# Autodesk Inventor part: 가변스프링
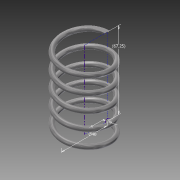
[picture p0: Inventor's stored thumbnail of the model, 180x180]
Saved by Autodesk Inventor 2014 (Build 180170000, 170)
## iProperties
Created: 2017-01
Part Number: 가변스프링
Material: Stainless Steel
Document SubType Name: Modeling
Designer: user
Density: 8.08 g/cm^3
Appearance: Semi-Polished
Mass: 62.9918 g
Surface Area: 78.9831 cm^2
Volume: 7.79602 cm^3
Author: user
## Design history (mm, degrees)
sketch "Sketch1"
  geometry: L1 (0, 0)-(20, 0); L2 (20, 0)-(20, 67.25); L3 (20, 67.25)-(0, 67.25); L4 (0, 67.25)-(0, 0); C1 r 2 at (20, 0)
  constraints: 8 end point, 2 parallel, 1 centre point, 1 coincident, 1 horizontal, 1 perpendicular
  dimensions: "d0" = 40 diameter of L2 L4; "d1" = 67.25 distance between parallel lines of L3 L1 (derived); "d2" = 4 diameter of C1
coil "Coil1" pitch "d3" = 10; turns "d5" = 5; dims "d4" = 67.25 (= d1), "d6" = 0, angle "d7" = 90 deg, angle "d8" = 90 deg, "d9" = 0, "d10" = 0
sketch "Sketch2"
  geometry: L1 (0, 18)-(0, 22) reference; 1 further point
  constraints: 1 vertical alignment
extrude "Extrusion1" cut sketch "Sketch2" distance "d11" = 10; taper "d12" = 0 deg
workplane "Work Plane1"
sketch "Sketch3"
  geometry: L1 (0, 18)-(0, 22) reference; 1 further point
  constraints: 1 vertical alignment
extrude "Extrusion2" cut sketch "Sketch3" distance "d13" = 10; taper "d14" = 0 deg
body "Solid1"
node "Project Cut Edges1"
node "Project Cut Edges2"
